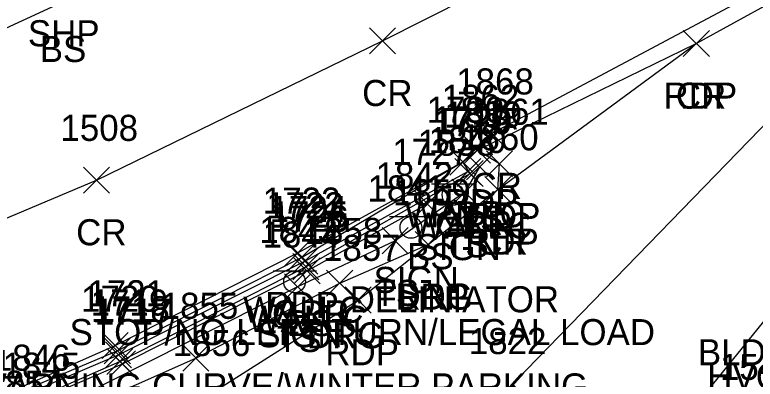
# Model space of a CAD drawing. Extents: x 1657482 to 1661439, y 647981 to 649041.
# Drawn here: x 1659950.7 to 1660007.4, y 648104.7 to 648132.6 of the extents above; entities that cross this region are included whole.
import ezdxf

# ---------------------------------------------------------------- set-up
doc = ezdxf.new("R2010")
doc.units = 0
for name, color, linetype in [('C_A', 7, 'Continuous'), ('L_A', 7, 'Continuous'), ('L_I', 7, 'Continuous'), ('L_TIC', 7, 'Continuous'), ('LELB', 7, 'Continuous'), ('LW', 7, 'Continuous'), ('P_A', 7, 'Continuous'), ('P_I', 7, 'Continuous'), ('P_TIC', 7, 'Continuous'), ('PET', 7, 'Continuous'), ('PRC', 7, 'Continuous'), ('R_A', 7, 'Continuous'), ('R_I', 7, 'Continuous'), ('R_TIC', 7, 'Continuous'), ('RDG', 7, 'Continuous'), ('RGR', 7, 'Continuous'), ('S_A', 7, 'Continuous'), ('S_C', 7, 'Continuous'), ('S_I', 7, 'Continuous'), ('SSGN', 7, 'Continuous'), ('U_I', 7, 'Continuous')]:
    doc.layers.add(name, color=color, linetype=linetype)

msp = doc.modelspace()

# ---------------------------------------------------------------- linework, layer by layer
at = {"layer": 'L_TIC'}
for points in [[(1659984.018, 648120.317), (1659986.018, 648122.317)], [(1659986.018, 648120.317), (1659984.018, 648122.317)], [(1659984.018, 648120.317), (1659986.018, 648122.317)], [(1659986.018, 648120.317), (1659984.018, 648122.317)], [(1659985.305, 648119.95), (1659987.305, 648121.95)], [(1659987.305, 648119.95), (1659985.305, 648121.95)], [(1659984.568, 648119.441), (1659986.568, 648121.441)], [(1659986.568, 648119.441), (1659984.568, 648121.441)], [(1659984.172, 648117.997), (1659986.172, 648119.997)], [(1659986.172, 648117.997), (1659984.172, 648119.997)], [(1659981.3, 648117.095), (1659983.3, 648119.095)], [(1659983.3, 648117.095), (1659981.3, 648119.095)], [(1659978.834, 648114.284), (1659980.834, 648116.284)], [(1659980.834, 648114.284), (1659978.834, 648116.284)], [(1659971.638, 648112.994), (1659973.638, 648114.994)], [(1659973.638, 648112.994), (1659971.638, 648114.994)], [(1659971.984, 648112.291), (1659973.984, 648114.291)], [(1659973.984, 648112.291), (1659971.984, 648114.291)], [(1659972.072, 648111.969), (1659974.072, 648113.969)], [(1659974.072, 648111.969), (1659972.072, 648113.969)], [(1659971.354, 648110.752), (1659973.354, 648112.752)], [(1659973.354, 648110.752), (1659971.354, 648112.752)], [(1659957.528, 648105.836), (1659959.528, 648107.836)], [(1659959.528, 648105.836), (1659957.528, 648107.836)], [(1659957.73, 648105.028), (1659959.73, 648107.028)], [(1659959.73, 648105.028), (1659957.73, 648107.028)], [(1659957.93, 648104.84), (1659959.93, 648106.84)], [(1659959.93, 648104.84), (1659957.93, 648106.84)]]:
    msp.add_lwpolyline(points, dxfattribs=at)
at = {"layer": 'LELB'}
for points in [[(1659986.305, 648120.95), (1659985.172, 648118.997), (1659979.834, 648115.284), (1659972.354, 648111.752), (1659952.425, 648101.706), (1659944.177, 648097.111), (1659941.553, 648091.094)], [(1659941.563, 648090.011), (1659932.825, 648094.181), (1659931.212, 648094.992), (1659935.607, 648096.348), (1659946.529, 648100.532), (1659958.93, 648105.84), (1659973.072, 648112.969), (1659982.3, 648118.095)]]:
    msp.add_lwpolyline(points, dxfattribs=at)
at = {"layer": 'LW'}
for points in [[(1659941.286, 648090.013), (1659940.99, 648089.386), (1659930.702, 648094.209), (1659928.279, 648095.139), (1659928.276, 648095.282), (1659930.501, 648095.819), (1659935.416, 648097.611), (1659946.777, 648101.881), (1659958.528, 648106.836), (1659972.638, 648113.994), (1659985.018, 648121.317)], [(1659941.286, 648090.013), (1659930.836, 648095.132), (1659935.508, 648096.624), (1659946.638, 648100.742), (1659958.73, 648106.028), (1659972.984, 648113.291), (1659985.568, 648120.441), (1659985.018, 648121.317)]]:
    msp.add_lwpolyline(points, dxfattribs=at)
at = {"layer": 'P_TIC'}
for points in [[(1659977.865, 648129.6), (1659979.865, 648131.6)], [(1659979.865, 648129.6), (1659977.865, 648131.6)], [(1660001.916, 648129.398), (1660003.916, 648131.398)], [(1660003.916, 648129.398), (1660001.916, 648131.398)], [(1660001.916, 648129.398), (1660003.916, 648131.398)], [(1660003.916, 648129.398), (1660001.916, 648131.398)], [(1659986.25, 648122.488), (1659988.25, 648124.488)], [(1659988.25, 648122.488), (1659986.25, 648124.488)], [(1659985.135, 648121.233), (1659987.135, 648123.233)], [(1659987.135, 648121.233), (1659985.135, 648123.233)], [(1659985.135, 648121.233), (1659987.135, 648123.233)], [(1659987.135, 648121.233), (1659985.135, 648123.233)], [(1659984.018, 648120.317), (1659986.018, 648122.317)], [(1659986.018, 648120.317), (1659984.018, 648122.317)], [(1659986.831, 648120.168), (1659988.831, 648122.168)], [(1659988.831, 648120.168), (1659986.831, 648122.168)], [(1659955.941, 648118.929), (1659957.941, 648120.929)], [(1659957.941, 648118.929), (1659955.941, 648120.929)], [(1659986.705, 648118.209), (1659988.705, 648120.209)], [(1659988.705, 648118.209), (1659986.705, 648120.209)], [(1659986.705, 648118.209), (1659988.705, 648120.209)], [(1659988.705, 648118.209), (1659986.705, 648120.209)], [(1659981.362, 648113.995), (1659983.362, 648115.995)], [(1659983.362, 648113.995), (1659981.362, 648115.995)], [(1659971.375, 648113.357), (1659973.375, 648115.357)], [(1659973.375, 648113.357), (1659971.375, 648115.357)], [(1659975.988, 648109.733), (1659977.988, 648111.733)], [(1659977.988, 648109.733), (1659975.988, 648111.733)], [(1659957.358, 648106.252), (1659959.358, 648108.252)], [(1659959.358, 648106.252), (1659957.358, 648108.252)]]:
    msp.add_lwpolyline(points, dxfattribs=at)
at = {"layer": 'PET'}
for points in [[(1659797.957, 648111.988), (1659819.59, 648111.147), (1659820.376, 648114.717), (1659842.939, 648112.708), (1659860.056, 648111.284), (1659870.084, 648111.395), (1659880.312, 648111.43), (1659885.231, 648111.845), (1659895.84, 648113.342), (1659903.958, 648115.551), (1659911.843, 648118.071), (1659934.128, 648124.4), (1659939.783, 648126.971), (1659944.648, 648129.118), (1659977.635, 648144.34), (1659987.87, 648149.672), (1659995.671, 648153.846), (1660001.577, 648157.024), (1660026.061, 648170.189)], [(1659799.28, 648086.136), (1659822.829, 648084.094), (1659841.236, 648083.238), (1659849.285, 648082.699), (1659853.297, 648081.633), (1659863.28, 648081.701), (1659871.418, 648082.62), (1659885.552, 648085.022), (1659891.684, 648086.345), (1659901.533, 648088.7), (1659915.482, 648092.509), (1659918.893, 648092.262), (1659919.908, 648093.139), (1659925.791, 648090.399), (1659928.096, 648095.554), (1659935.247, 648097.751), (1659946.62, 648102.053), (1659958.358, 648107.252), (1659972.375, 648114.357), (1659985.018, 648121.317), (1659986.135, 648122.233), (1660002.916, 648130.398), (1660023.122, 648141.511)], [(1659863.28, 648081.701), (1659868.598, 648080.447), (1659876.948, 648078.161), (1659883.344, 648076.024), (1659889.16, 648073.962), (1659894.185, 648071.763), (1659897.898, 648070.646), (1659905.34, 648067.906), (1659912.798, 648065.014), (1659924.735, 648059.408), (1659938.824, 648053.114), (1659959.475, 648042.397), (1659969.15, 648037.003), (1659978.866, 648031.627), (1659984.71, 648040.852), (1659990.854, 648049.845), (1659987.428, 648053.134), (1659983.709, 648058.695), (1659981.789, 648065.569), (1659981.786, 648070.317), (1659983.864, 648077.674), (1659998.695, 648097.495), (1660020.131, 648123.934)], [(1659918.893, 648092.262), (1659926.687, 648088.418), (1659938.953, 648083.445), (1659939.381, 648084.566), (1659940.975, 648089.092), (1659941.563, 648090.011), (1659947.038, 648088.96), (1659950.322, 648090.765), (1659954.348, 648094.635), (1659965.527, 648103.437), (1659976.988, 648110.733), (1659982.362, 648114.995), (1659987.705, 648119.209), (1659987.831, 648121.168), (1659986.135, 648122.233)]]:
    msp.add_lwpolyline(points, dxfattribs=at)
at = {"layer": 'PRC'}
for points in [[(1659666.144, 648110.534), (1659699.551, 648107.376), (1659729.526, 648104.331), (1659765.503, 648101.141), (1659792.988, 648098.376), (1659818.732, 648097.206), (1659849.225, 648095.841), (1659870.331, 648096.361), (1659894.597, 648099.456), (1659913.112, 648103.656), (1659935.294, 648110.794), (1659956.941, 648119.929), (1659978.865, 648130.6), (1660002.085, 648142.328), (1660031.609, 648158.263), (1660061.231, 648174.691), (1660097.076, 648195.768), (1660113.884, 648205.485), (1660151.727, 648227.302), (1660188.688, 648248.658)], [(1660054.019, 648158.569), (1660030.986, 648147.191), (1660013.192, 648137.349), (1659987.25, 648123.488)], [(1659963.459, 648069.889), (1659971.311, 648084.482), (1659988.169, 648103.589), (1660012.915, 648129.083), (1660023.122, 648141.511)], [(1659987.705, 648119.209), (1660002.916, 648130.398)]]:
    msp.add_lwpolyline(points, dxfattribs=at)
at = {"layer": 'R_TIC'}
for points in [[(1659984.391, 648119.585), (1659986.391, 648121.585)], [(1659986.391, 648119.585), (1659984.391, 648121.585)], [(1659981.362, 648113.995), (1659983.362, 648115.995)], [(1659983.362, 648113.995), (1659981.362, 648115.995)], [(1659971.897, 648112.712), (1659973.897, 648114.712)], [(1659973.897, 648112.712), (1659971.897, 648114.712)], [(1659974.578, 648111.028), (1659976.578, 648113.028)], [(1659976.578, 648111.028), (1659974.578, 648113.028)], [(1659957.619, 648105.542), (1659959.619, 648107.542)], [(1659959.619, 648105.542), (1659957.619, 648107.542)], [(1659963.546, 648105.291), (1659965.546, 648107.291)], [(1659965.546, 648105.291), (1659963.546, 648107.291)]]:
    msp.add_lwpolyline(points, dxfattribs=at)
at = {"layer": 'RDG'}
msp.add_lwpolyline([(1659944.082, 648090.155), (1659945.939, 648096.438), (1659951.126, 648100.323), (1659964.546, 648106.291), (1659975.578, 648112.028), (1659982.362, 648114.995)], dxfattribs=at)
at = {"layer": 'RGR'}
msp.add_lwpolyline([(1659931.702, 648096.032), (1659946.527, 648101.393), (1659958.619, 648106.542), (1659972.897, 648113.712), (1659985.391, 648120.585)], dxfattribs=at)
at = {"layer": 'SSGN'}
for p, q in [((1659982.615, 648119.644), (1659985.948, 648119.644)), ((1659984.262, 648118.811), (1659984.262, 648118.811)), ((1659979.391, 648117.13), (1659982.724, 648117.13)), ((1659981.038, 648116.297), (1659981.038, 648116.297)), ((1659970.472, 648112.965), (1659973.805, 648112.965)), ((1659972.119, 648112.131), (1659972.119, 648112.131))]:
    msp.add_line(p, q, dxfattribs=at)
for centre in [(1659984.262, 648118.811), (1659981.038, 648116.297), (1659972.119, 648112.131)]:
    msp.add_circle(centre, 0.833, dxfattribs=at)

# ---------------------------------------------------------------- texts
at = {"layer": 'C_A'}
msp.add_text('HVCTRL', height=2, dxfattribs=at).set_placement((1660003.755, 648103.881))
at = {"layer": 'L_A'}
for s, p in [('BS', (1659952.583, 648128.978)), ('BS', (1659952.583, 648128.978)), ('WALLC', (1659980.553, 648116.317)), ('WALLC', (1659980.553, 648116.317)), ('TS', (1659984.714, 648115.95)), ('WALLC', (1659981.103, 648115.441)), ('TS', (1659983.581, 648113.997)), ('BS', (1659980.741, 648113.095)), ('TS', (1659978.244, 648110.284)), ('WALLC', (1659968.174, 648108.994)), ('WALLC', (1659968.519, 648108.291)), ('BS', (1659971.513, 648107.969)), ('TS', (1659970.763, 648106.752)), ('BLDG STPS ST', (1660003.032, 648105.734))]:
    msp.add_text(s, height=2, dxfattribs=at).set_placement(p)
at = {"layer": 'L_I'}
for s, p in [('1730', (1659982.239, 648124.317)), ('1730', (1659982.239, 648124.317)), ('1839', (1659983.604, 648123.95)), ('1729', (1659982.867, 648123.441)), ('1840', (1659982.393, 648121.997)), ('1727', (1659979.608, 648121.095)), ('1841', (1659977.708, 648118.284)), ('1723', (1659969.945, 648116.994)), ('1725', (1659970.291, 648116.291)), ('1726', (1659970.324, 648115.969)), ('1844', (1659969.661, 648114.752)), ('1720', (1659955.748, 648109.836)), ('1718', (1659956.604, 648109.028)), ('1717', (1659956.804, 648108.84)), ('1856', (1659962.779, 648106.437)), ('1845', (1659949.733, 648104.706)), ('1540', (1660004.725, 648104.608))]:
    msp.add_text(s, height=2, dxfattribs=at).set_placement(p)
at = {"layer": 'P_A'}
for s, p in [('SHP', (1659951.673, 648130.182)), ('CR', (1659977.298, 648125.6)), ('RDP', (1660000.404, 648125.398)), ('CR', (1660001.349, 648125.398)), ('CR', (1659985.683, 648118.488)), ('RDP', (1659983.624, 648117.233)), ('RDP', (1659983.624, 648117.233)), ('RDP', (1659982.506, 648116.317)), ('RDP', (1659985.319, 648116.168)), ('CR', (1659955.374, 648114.929)), ('RDP', (1659985.193, 648114.209)), ('CR', (1659986.138, 648114.209)), ('RDP', (1659979.85, 648109.995)), ('RDP', (1659969.863, 648109.357)), ('RDP', (1659974.476, 648105.733))]:
    msp.add_text(s, height=2, dxfattribs=at).set_placement(p)
at = {"layer": 'P_I'}
for s, p in [('1868', (1659984.51, 648126.488)), ('1862', (1659983.395, 648125.233)), ('1862', (1659983.395, 648125.233)), ('1730', (1659982.239, 648124.317)), ('1861', (1659985.658, 648124.168)), ('1508', (1659954.17, 648122.929)), ('1860', (1659984.878, 648122.209)), ('1860', (1659984.878, 648122.209)), ('1859', (1659979.662, 648117.995)), ('1722', (1659969.682, 648117.357)), ('1857', (1659974.295, 648113.733)), ('1721', (1659956.232, 648110.252)), ('1856', (1659962.779, 648106.437)), ('1822', (1659985.477, 648106.589))]:
    msp.add_text(s, height=2, dxfattribs=at).set_placement(p)
at = {"layer": 'R_A'}
for s, p in [('GRR', (1659982.879, 648115.585)), ('DRG', (1659979.85, 648109.995)), ('GRR', (1659970.385, 648108.712)), ('DRG', (1659973.066, 648107.028))]:
    msp.add_text(s, height=2, dxfattribs=at).set_placement(p)
at = {"layer": 'R_I'}
for s, p in [('1728', (1659982.698, 648123.585)), ('1859', (1659979.662, 648117.995)), ('1724', (1659970.204, 648116.712)), ('1858', (1659972.885, 648115.028)), ('1719', (1659956.486, 648109.542)), ('1855', (1659961.853, 648109.291)), ('1854', (1659948.434, 648103.323))]:
    msp.add_text(s, height=2, dxfattribs=at).set_placement(p)
at = {"layer": 'S_A'}
for p in [(1659981.4, 648113.79), (1659978.176, 648111.276), (1659969.257, 648107.111)]:
    msp.add_text('SIGN', height=2, dxfattribs=at).set_placement(p)
at = {"layer": 'S_C'}
for s, p in [('DELINIATOR', (1659976.345, 648109.79)), ('STOP/NO LEFT TURN/LEGAL LOAD', (1659954.869, 648107.276)), ('WARNING CURVE/WINTER PARKING', (1659947.525, 648103.111))]:
    msp.add_text(s, height=2, dxfattribs=at).set_placement(p)
at = {"layer": 'S_I'}
for s, p in [('1838', (1659981.549, 648121.79)), ('1842', (1659978.325, 648119.276)), ('1843', (1659969.406, 648115.111))]:
    msp.add_text(s, height=2, dxfattribs=at).set_placement(p)
at = {"layer": 'U_I'}
msp.add_text('1846', height=2, dxfattribs=at).set_placement((1659948.986, 648105.318))

doc.saveas('drawing.dxf')
